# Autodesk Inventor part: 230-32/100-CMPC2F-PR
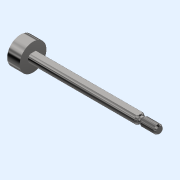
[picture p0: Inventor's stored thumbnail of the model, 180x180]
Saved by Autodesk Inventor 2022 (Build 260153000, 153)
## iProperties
Part Number: 230-32/100-CMPC2F-PR
Material: Generico
Catalog Web Link: www.cadenas.de
Description: CMPC2F-PR-
Vendor: METALWORK
Document SubType Name: Modeling
Designer: partserver
Manufacturer: METALWORK
Mass: 27.1141 g
Surface Area: 85.4493 cm^2
Volume: 27.1141 cm^3
Density: 1 g/cm^3
Appearance: Acciaio - Lucido
Category: PARTsolutions
Company: METALWORK
PSOL_IDENT_0: {$CADENAS_DATA\23d-libs\metalwork\actuators\comp_cyl_ser_cmpc_2_flat\parts\cmpc_2_flat_piston_rod.pr
PSOL_IDENT_1: j},202 {VTYP=3D},{NB=230-32/100-CMPC2F-PR},{LINA=230-32/100-CMPC2F-PR},{NN=CMPC2F-PR},{DATE=18.06.20
PSOL_IDENT_2: 21 08:06:07},{GEOMDATE=01.12.2009 08:11:00},{VERSION=},{LINEID=50},{WBVAR=TYPE,VE,HUB},{WBNUMERIC=TY
PSOL_IDENT_3: PE,HUB}  {NB=230-32/100-CMPC2F-PR},{LINA=230-32/100-CMPC2F-PR},{KT=DUMMY},{IDNR=},{TYPE=23},{VE=0},{
PSOL_IDENT_4: HUB=100},{DI=32.000},{C=12.000},{C1=9.000},{CH=10.000},{G=44.500},{HH=14.750},{M=14.000},{N=59.500},
PSOL_IDENT_5: {P=6.000},{R=10.000},{RP=1.250},{S=22.000},{CD=11.000},{CL=5.600},{CL2=2.500},{RCH=2.000}
NB: 230-32/100-CMPC2F-PR
NN: CMPC2F-PR
NBSYN: $TYPE.$VE.-$DI./$HUB.-CMPC2F-PR
LINA: 230-32/100-CMPC2F-PR
CATALOG: Metalwork
TYPE: Centre distance to UNITOP, male rod
VE: Double-acting
HUB: 100
DI: 32
C: 12
C1: 9
CH: 10
G: 44.5
HH: 14.75
M: 14
N: 59.5
P: 6
R: 10
RP: 1.25
S: 22
CD: 11
CL: 5.6
CL2: 2.5
RCH: 2
SUPPLIER: METALWORK
ARTICLENO: 230-32/100-CMPC2F-PR
BOMINFO: 230-32/100-CMPC2F-PR
CREATOR: CADENAS GmbH
Title: 230-32/100-CMPC2F-PR
Author: Cadenas PARTsolutions
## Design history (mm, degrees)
sketch "Sketch_1"
  geometry: L1 (7.5, 0)-(-137.25, 0); L2 (-137.25, 0)-(-137.25, 4.557); L3 (-137.25, 4.557)-(-134.75, 6); L4 (-134.75, 6)-(-7.5, 6); L5 (-7.5, 6)-(-7.5, 16); L6 (-7.5, 16)-(7.5, 16); L7 (7.5, 16)-(7.5, 0); L8 (7.5, 0)-(-137.25, 0)
  constraints: 16 end point
revolve "Revolution1" sketch "Sketch_1" stored, may be unused: angle "d0" = 360 deg
sketch "Sketch_3"
  geometry: L1 (-20, -10)-(20, -10); L2 (20, -10)-(20, 10); L3 (20, 10)-(-20, 10); L4 (-20, 10)-(-20, -10); L5 (-10, -5)-(10, -5); L6 (10, -5)-(10, 5); L7 (10, 5)-(-10, 5); L8 (-10, 5)-(-10, -5)
  constraints: 16 end point
extrude "Extrusion1" cut sketch "Sketch_3" distance "d1" = 129.75; taper "d2" = 0 deg
sketch "Sketch_5"
  geometry: L1 (-137.25, 0)-(-159.25, 0); L2 (-159.25, 0)-(-159.25, 3.845); L3 (-159.25, 3.845)-(-157.25, 5); L4 (-157.25, 5)-(-141.45, 5); L5 (-141.45, 5)-(-139.45, 3.845); L6 (-139.45, 3.845)-(-137.25, 3.845); L7 (-137.25, 3.845)-(-137.25, 0); L8 (-137.25, 0)-(-159.25, 0)
  constraints: 16 end point
revolve "Revolution2" sketch "Sketch_5" stored, may be unused: angle "d3" = 360 deg
thread "Thread1" dims "d4" = 15.8, "d5" = 0
node "rod_XY"
node "rod_YZ"
node "rod_ZX"
node "rod_X"
node "rod_Y"
node "rod_Z"
node "rod_Center"
node "rod_acc_l_XY"
node "rod_acc_l_YZ"
node "rod_acc_l_ZX"
node "rod_acc_l_X"
node "rod_acc_l_Y"
node "rod_acc_l_Z"
node "rod_acc_l_Center"
body "Solid1"
other parameters: "d6" = 0
